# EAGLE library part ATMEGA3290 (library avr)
MICROCONTROLLER 32 Kbytes FLASH 2 Kbytes SRAM 1 Kbytes EEPROM USART 8-channel 10 bit ADC LCD Driver
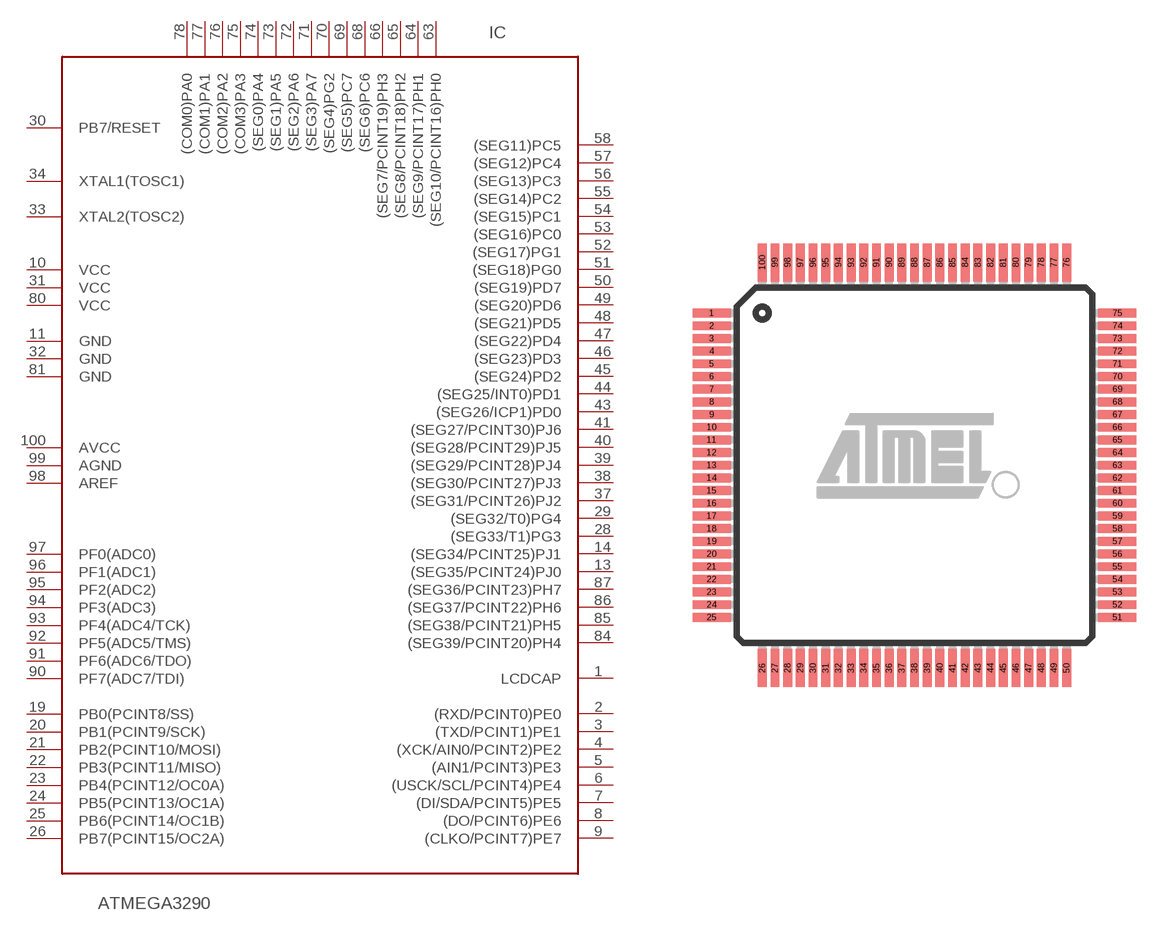
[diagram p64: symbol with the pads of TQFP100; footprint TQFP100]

Designator prefix IC

## ATMEGA3290-16A, ATMEGA3290V-8A  [TQFP100]
1  LCDCAP
2  (RXD/PCINT0)PE0
3  (TXD/PCINT1)PE1
4  (XCK/AIN0/PCINT2)PE2
5  (AIN1/PCINT3)PE3
6  (USCK/SCL/PCINT4)PE4
7  (DI/SDA/PCINT5)PE5
8  (DO/PCINT6)PE6
9  (CLKO/PCINT7)PE7
10  VCC  pwr
11  GND  pwr
12  P$57  nc
13  (SEG35/PCINT24)PJ0
14  (SEG34/PCINT25)PJ1
15  P$58  nc
16  P$59  nc
17  P$60  nc
18  P$61  nc
19  PB0(PCINT8/SS)  nc
20  PB1(PCINT9/SCK)  nc
21  PB2(PCINT10/MOSI)  nc
22  PB3(PCINT11/MISO)  nc
23  PB4(PCINT12/OC0A)  nc
24  PB5(PCINT13/OC1A)  nc
25  PB6(PCINT14/OC1B)  nc
26  PB7(PCINT15/OC2A)
27  P$62  nc
28  (SEG33/T1)PG3
29  (SEG32/T0)PG4
30  PB7/RESET  nc
31  VCC  pwr
32  GND  pwr
33  XTAL2(TOSC2)
34  XTAL1(TOSC1)
35  P$63  nc
36  P$64  nc
37  (SEG31/PCINT26)PJ2
38  (SEG30/PCINT27)PJ3
39  (SEG29/PCINT28)PJ4
40  (SEG28/PCINT29)PJ5
41  (SEG27/PCINT30)PJ6
42  P$65  nc
43  (SEG26/ICP1)PD0
44  (SEG25/INT0)PD1
45  (SEG24)PD2
46  (SEG23)PD3
47  (SEG22)PD4
48  (SEG21)PD5
49  (SEG20)PD6
50  (SEG19)PD7
51  (SEG18)PG0
52  (SEG17)PG1
53  (SEG16)PC0
54  (SEG15)PC1
55  (SEG14)PC2
56  (SEG13)PC3
57  (SEG12)PC4
58  (SEG11)PC5
59  P$66  nc
60  P$67  nc
61  P$68  nc
62  P$69  nc
63  (SEG10/PCINT16)PH0
64  (SEG9/PCINT17)PH1
65  (SEG8/PCINT18)PH2
66  (SEG7/PCINT19)PH3
67  P$70  nc
68  (SEG6)PC6
69  (SEG5)PC7
70  (SEG4)PG2
71  (SEG3)PA7
72  (SEG2)PA6
73  (SEG1)PA5
74  (SEG0)PA4
75  (COM3)PA3
76  (COM2)PA2
77  (COM1)PA1
78  (COM0)PA0
79  P$71  nc
80  VCC  pwr
81  GND  pwr
82  P$72  nc
83  P$73  nc
84  (SEG39/PCINT20)PH4
85  (SEG38/PCINT21)PH5
86  (SEG37/PCINT22)PH6
87  (SEG36/PCINT23)PH7
88  P$74  nc
89  P$75  nc
90  PF7(ADC7/TDI)  nc
91  PF6(ADC6/TDO)  nc
92  PF5(ADC5/TMS)  nc
93  PF4(ADC4/TCK)  nc
94  PF3(ADC3)  nc
95  PF2(ADC2)  nc
96  PF1(ADC1)  nc
97  PF0(ADC0)  nc
98  AREF  pwr
99  AGND  pwr
100  AVCC  pwr

## Footprint TQFP100 (pad centres in mm)
100-lead Thin Quad Flat Pack Package Outline
smd 1.5 x 0.35: 1 -8,6; 2 -8,5.5; 3 -8,5; 4 -8,4.5; 5 -8,4; 6 -8,3.5; 7 -8,3; 8 -8,2.5; 9 -8,2; 10 -8,1.5; 11 -8,1; 12 -8,0.5; 13 -8,0; 14 -8,-0.5; 15 -8,-1; 16 -8,-1.5; 17 -8,-2; 18 -8,-2.5; 19 -8,-3; 20 -8,-3.5; 21 -8,-4; 22 -8,-4.5; 23 -8,-5; 24 -8,-5.5; 25 -8,-6; 51 8,-6; 52 8,-5.5; 53 8,-5; 54 8,-4.5; 55 8,-4; 56 8,-3.5; 57 8,-3; 58 8,-2.5; 59 8,-2; 60 8,-1.5; 61 8,-1; 62 8,-0.5; 63 8,0; 64 8,0.5; 65 8,1; 66 8,1.5; 67 8,2; 68 8,2.5; 69 8,3; 70 8,3.5; 71 8,4; 72 8,4.5; 73 8,5; 74 8,5.5; 75 8,6
smd 0.35 x 1.5: 26 -6,-8; 27 -5.5,-8; 28 -5,-8; 29 -4.5,-8; 30 -4,-8; 31 -3.5,-8; 32 -3,-8; 33 -2.5,-8; 34 -2,-8; 35 -1.5,-8; 36 -1,-8; 37 -0.5,-8; 38 0,-8; 39 0.5,-8; 40 1,-8; 41 1.5,-8; 42 2,-8; 43 2.5,-8; 44 3,-8; 45 3.5,-8; 46 4,-8; 47 4.5,-8; 48 5,-8; 49 5.5,-8; 50 6,-8; 76 6,8; 77 5.5,8; 78 5,8; 79 4.5,8; 80 4,8; 81 3.5,8; 82 3,8; 83 2.5,8; 84 2,8; 85 1.5,8; 86 1,8; 87 0.5,8; 88 0,8; 89 -0.5,8; 90 -1,8; 91 -1.5,8; 92 -2,8; 93 -2.5,8; 94 -3,8; 95 -3.5,8; 96 -4,8; 97 -4.5,8; 98 -5,8; 99 -5.5,8; 100 -6,8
